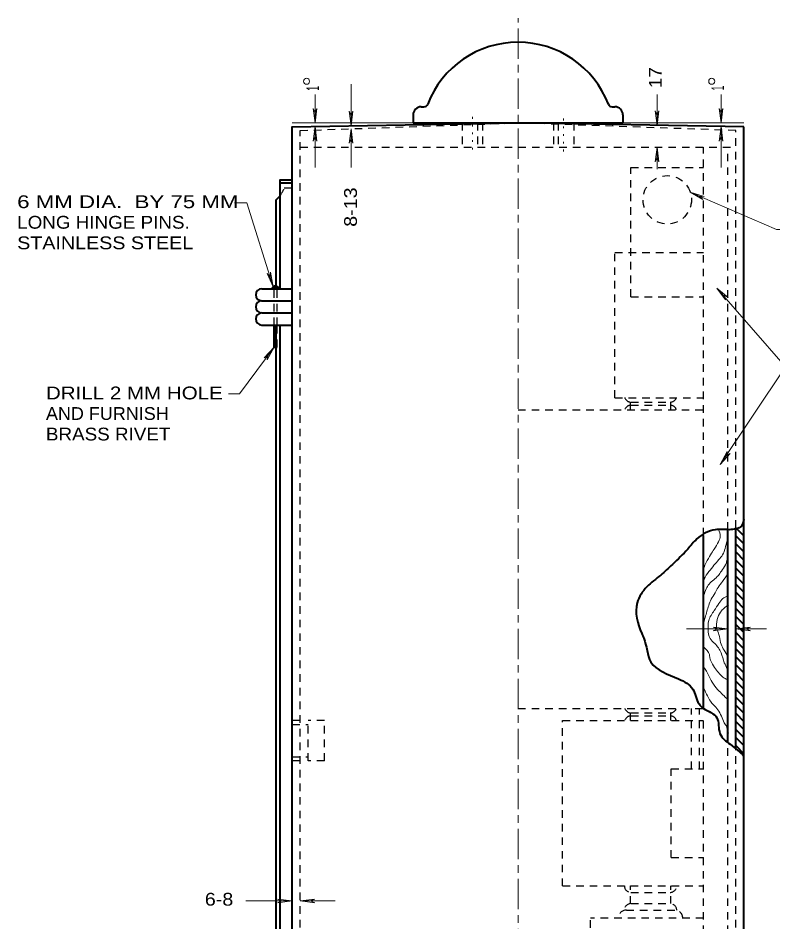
# Model space of a CAD drawing. Extents: x 312583 to 312853, y 144419 to 144586.
# Drawn here: x 312673.6 to 312718.5, y 144473.4 to 144527 of the extents above; entities that cross this region are included whole.
import ezdxf

# ---------------------------------------------------------------- set-up
doc = ezdxf.new("R2010")
doc.units = 0
doc.header["$LTSCALE"] = 0.3
for name, pattern in [('DOTTED', [1.5, 0.3, -1.2]), ('LONG_DASH_SHORT_DASH', [9.9, 6, -1.2, 1.5, -1.2]), ('SHORT_DASHED', [2.7, 1.5, -1.2])]:
    doc.linetypes.add(name, pattern=pattern)
doc.layers.add('1', color=7, linetype='Continuous', lineweight=13)

msp = doc.modelspace()

# ---------------------------------------------------------------- linework, layer by layer
at = {"layer": '1', "linetype": 'LONG_DASH_SHORT_DASH'}
msp.add_line((312703.3115, 144441.4612), (312703.3115, 144527.0365), dxfattribs=at)
at = {"layer": '1'}
for p, q in [((312693.3909, 144520.6349), (312693.3909, 144523.1046)), ((312691.2519, 144520.8112), (312691.2519, 144522.5055)), ((312711.5685, 144520.6655), (312711.5685, 144522.5055)), ((312715.3712, 144520.8112), (312715.3712, 144522.5055)), ((312691.1445, 144521.6775), (312691.2519, 144521.4015)), ((312691.2519, 144520.8112), (312691.1445, 144521.6775)), ((312691.3592, 144521.6775), (312691.2519, 144521.4015)), ((312691.2519, 144520.8112), (312691.3592, 144521.6775)), ((312693.2835, 144521.5012), (312693.3909, 144521.2252)), ((312693.3909, 144520.6349), (312693.2835, 144521.5012)), ((312693.4982, 144521.5012), (312693.3909, 144521.2252)), ((312693.3909, 144520.6349), (312693.4982, 144521.5012)), ((312711.4612, 144521.5319), (312711.5685, 144521.2559)), ((312711.5685, 144520.6655), (312711.4612, 144521.5319)), ((312711.6759, 144521.5319), (312711.5685, 144521.2559)), ((312711.5685, 144520.6655), (312711.6759, 144521.5319)), ((312715.2639, 144521.6775), (312715.3712, 144521.4015)), ((312715.3712, 144520.8112), (312715.2639, 144521.6775)), ((312715.4785, 144521.6775), (312715.3712, 144521.4015)), ((312715.3712, 144520.8112), (312715.4785, 144521.6775)), ((312703.3115, 144520.8112), (312689.8949, 144520.8112)), ((312703.3115, 144520.8112), (312716.7282, 144520.8112)), ((312691.2519, 144520.5965), (312691.1445, 144519.7302)), ((312691.2519, 144518.1585), (312691.2519, 144520.5965)), ((312691.2519, 144520.5965), (312691.3592, 144519.7302)), ((312693.3909, 144520.4662), (312693.2835, 144519.5999)), ((312693.3909, 144518.1585), (312693.3909, 144520.4662)), ((312693.3909, 144520.4662), (312693.4982, 144519.5999)), ((312715.3712, 144520.5965), (312715.2639, 144519.7302)), ((312715.3712, 144518.1585), (312715.3712, 144520.5965)), ((312715.3712, 144520.5965), (312715.4785, 144519.7302)), ((312691.1445, 144519.7302), (312691.2519, 144520.0062)), ((312691.3592, 144519.7302), (312691.2519, 144520.0062)), ((312693.2835, 144519.5999), (312693.3909, 144519.8759)), ((312693.4982, 144519.5999), (312693.3909, 144519.8759)), ((312715.2639, 144519.7302), (312715.3712, 144520.0062)), ((312715.4785, 144519.7302), (312715.3712, 144520.0062)), ((312711.5685, 144519.3699), (312711.4612, 144518.5035)), ((312711.5685, 144518.0742), (312711.5685, 144519.3699)), ((312711.5685, 144519.3699), (312711.6759, 144518.5035)), ((312711.4612, 144518.5035), (312711.5685, 144518.7795)), ((312711.6759, 144518.5035), (312711.5685, 144518.7795)), ((312713.5389, 144516.7095), (312714.2803, 144516.256)), ((312713.5389, 144516.7095), (312714.3663, 144516.4486)), ((312714.2803, 144516.256), (312714.0782, 144516.4665)), ((312714.3663, 144516.4486), (312714.0782, 144516.4665)), ((312686.4692, 144516.0732), (312687.2039, 144516.0732)), ((312688.7679, 144511.0822), (312687.2039, 144516.0732)), ((312688.4075, 144511.8795), (312688.5915, 144511.6419)), ((312688.7679, 144511.0822), (312688.4075, 144511.8795)), ((312688.6145, 144511.9409), (312688.5915, 144511.6419)), ((312688.7679, 144511.0822), (312688.6145, 144511.9409)), ((312715.1259, 144511.0055), (312715.6319, 144510.3002)), ((312715.1259, 144511.0055), (312715.7929, 144510.4459)), ((312715.6319, 144510.3002), (312715.5245, 144510.5762)), ((312715.7929, 144510.4459), (312715.5245, 144510.5762)), ((312688.8292, 144507.5019), (312686.7669, 144504.7265)), ((312688.8292, 144507.5019), (312688.2312, 144506.8655)), ((312688.8292, 144507.5019), (312688.3999, 144506.7429)), ((312688.2312, 144506.8655), (312688.4765, 144507.0265)), ((312688.3999, 144506.7429), (312688.4765, 144507.0265)), ((312686.1188, 144504.7265), (312686.7669, 144504.7265)), ((312715.3175, 144500.5329), (312715.7315, 144501.2995)), ((312715.3175, 144500.5329), (312715.9079, 144501.1769)), ((312715.7315, 144501.2995), (312715.6625, 144501.0159)), ((312715.9079, 144501.1769), (312715.6625, 144501.0159)), ((312713.3242, 144490.7655), (312715.7699, 144490.7655)), ((312714.9035, 144490.8729), (312715.1795, 144490.7655)), ((312715.7699, 144490.7655), (312714.9035, 144490.8729)), ((312714.9035, 144490.6582), (312715.1795, 144490.7655)), ((312715.7699, 144490.7655), (312714.9035, 144490.6582)), ((312716.2452, 144490.7655), (312717.1115, 144490.8729)), ((312716.2452, 144490.7655), (312718.0775, 144490.7655)), ((312716.2452, 144490.7655), (312717.1115, 144490.6582)), ((312717.1115, 144490.8729), (312716.8355, 144490.7655)), ((312717.1115, 144490.6582), (312716.8355, 144490.7655)), ((312687.1326, 144474.6195), (312689.8949, 144474.6195)), ((312689.0285, 144474.7269), (312689.3045, 144474.6195)), ((312689.8949, 144474.6195), (312689.0285, 144474.7269)), ((312689.0285, 144474.5122), (312689.3045, 144474.6195)), ((312689.8949, 144474.6195), (312689.0285, 144474.5122)), ((312690.3702, 144474.6195), (312691.2365, 144474.7269)), ((312690.3702, 144474.6195), (312692.4477, 144474.6195)), ((312690.3702, 144474.6195), (312691.2365, 144474.5122)), ((312691.2365, 144474.7269), (312690.9605, 144474.6195)), ((312691.2365, 144474.5122), (312690.9605, 144474.6195))]:
    msp.add_line(p, q, dxfattribs=at)
at = {"layer": '1', "lineweight": 40}
for p, q in [((312697.5615, 144521.7695), (312697.7225, 144521.7695)), ((312708.9005, 144521.7695), (312709.0615, 144521.7695)), ((312697.0785, 144521.2865), (312697.0785, 144520.8112)), ((312709.5369, 144521.2865), (312709.5369, 144520.8112)), ((312697.0785, 144520.8112), (312709.5369, 144520.8112)), ((312697.0785, 144520.8112), (312709.5369, 144520.8112)), ((312716.7282, 144520.5735), (312703.3115, 144520.8112)), ((312716.7282, 144443.8839), (312716.7282, 144520.5735)), ((312689.1742, 144517.2615), (312689.8949, 144517.2615)), ((312689.5192, 144517.4379), (312689.8949, 144517.4379)), ((312688.9365, 144510.9672), (312688.9365, 144516.2419)), ((312688.0932, 144510.9672), (312689.8949, 144510.9672)), ((312688.0932, 144510.2465), (312689.8949, 144510.2465)), ((312688.0932, 144509.5335), (312689.8949, 144509.5335)), ((312688.0932, 144508.8129), (312689.8949, 144508.8129)), ((312688.8292, 144507.5019), (312688.8292, 144508.8129)), ((312688.9365, 144462.3299), (312688.9365, 144508.8129)), ((312689.1742, 144462.3299), (312689.1742, 144508.8129)), ((312688.8292, 144507.5019), (312689.0132, 144507.5019)), ((312715.7699, 144484.0649), (312715.7699, 144496.6612)), ((312716.2452, 144483.6509), (312716.2452, 144496.7762)), ((312716.2452, 144496.7762), (312716.7282, 144496.3009)), ((312714.3285, 144486.0505), (312714.3285, 144496.3162)), ((312716.2452, 144496.3009), (312716.7282, 144495.8179)), ((312716.2452, 144495.8179), (312716.7282, 144495.3425)), ((312716.2452, 144495.3425), (312716.7282, 144494.8595)), ((312716.2452, 144494.8595), (312716.7282, 144494.3842)), ((312716.2452, 144494.3842), (312716.7282, 144493.9012)), ((312716.2452, 144493.9012), (312716.7282, 144493.4259)), ((312716.2452, 144493.4259), (312716.7282, 144492.9429)), ((312716.2452, 144492.9429), (312716.7282, 144492.4675)), ((312716.2452, 144492.4675), (312716.7282, 144491.9845)), ((312716.2452, 144491.9845), (312716.7282, 144491.5092)), ((312716.2452, 144491.5092), (312716.7282, 144491.0262)), ((312716.2452, 144491.0262), (312716.7282, 144490.5509)), ((312716.2452, 144490.5509), (312716.7282, 144490.0679)), ((312716.2452, 144490.0679), (312716.7282, 144489.5925)), ((312716.2452, 144489.5925), (312716.7282, 144489.1095)), ((312716.2452, 144489.1095), (312716.7282, 144488.6342)), ((312716.2452, 144488.6342), (312716.7282, 144488.1512)), ((312716.2452, 144488.1512), (312716.7282, 144487.6759)), ((312716.2452, 144487.6759), (312716.7282, 144487.1929)), ((312716.2452, 144487.1929), (312716.7282, 144486.7175)), ((312716.2452, 144486.7175), (312716.7282, 144486.2345)), ((312716.2452, 144486.2345), (312716.7282, 144485.7592)), ((312716.2452, 144485.7592), (312716.7282, 144485.2762)), ((312716.2452, 144485.2762), (312716.7282, 144484.8009)), ((312716.2452, 144484.8009), (312716.7282, 144484.3179)), ((312716.2452, 144484.3179), (312716.7282, 144483.8425)), ((312716.2452, 144483.8425), (312716.7282, 144483.3595))]:
    msp.add_line(p, q, dxfattribs=at)
at = {"layer": '1', "linetype": 'SHORT_DASHED', "lineweight": 25}
for p, q in [((312690.3702, 144520.3589), (312703.3115, 144520.8112)), ((312699.9995, 144520.8112), (312699.9995, 144519.3699)), ((312700.9119, 144520.8112), (312700.9119, 144519.3699)), ((312701.2032, 144520.8112), (312701.2032, 144519.3699)), ((312716.2452, 144520.3589), (312703.3115, 144520.8112)), ((312705.4199, 144520.8112), (312705.4199, 144519.3699)), ((312705.7035, 144520.8112), (312705.7035, 144519.3699)), ((312706.6235, 144520.8112), (312706.6235, 144519.3699)), ((312690.3702, 144443.8839), (312690.3702, 144520.3589)), ((312716.2452, 144496.7762), (312716.2452, 144520.3589)), ((312690.3702, 144519.3699), (312716.2452, 144519.3699)), ((312714.3285, 144496.3162), (312714.3285, 144519.3699)), ((312715.7699, 144496.6612), (312715.7699, 144519.3699)), ((312689.4272, 144516.9549), (312689.8949, 144516.9549)), ((312709.0615, 144513.1215), (312714.3285, 144513.1215)), ((312709.0615, 144504.4965), (312709.0615, 144513.1215)), ((312688.8292, 144508.8129), (312688.8292, 144510.9672)), ((312689.0132, 144508.8129), (312689.0132, 144510.9672)), ((312710.0199, 144510.4919), (312714.3285, 144510.4919)), ((312689.0132, 144507.5019), (312689.0132, 144508.8129)), ((312709.0615, 144504.4965), (312714.3285, 144504.4965)), ((312709.9815, 144503.7835), (312709.9815, 144504.4965)), ((312710.0199, 144504.2282), (312712.3505, 144504.2282)), ((312712.3812, 144503.7835), (312712.3812, 144504.4965)), ((312703.3115, 144503.7835), (312714.3285, 144503.7835)), ((312710.0199, 144504.0519), (312712.3505, 144504.0519)), ((312703.3115, 144486.0505), (312714.3285, 144486.0505)), ((312709.9815, 144485.3299), (312709.9815, 144486.0505)), ((312712.3812, 144485.3299), (312712.3812, 144486.0505)), ((312713.6155, 144482.4549), (312713.6155, 144486.0505)), ((312714.0909, 144482.4549), (312714.0909, 144486.0505)), ((312690.3702, 144485.3299), (312689.8949, 144485.3299)), ((312690.8532, 144482.9379), (312690.8532, 144485.3299)), ((312691.8115, 144485.3299), (312690.8532, 144485.3299)), ((312691.8115, 144482.9379), (312691.8115, 144485.3299)), ((312705.9489, 144485.3299), (312714.3285, 144485.3299)), ((312705.9489, 144475.5089), (312705.9489, 144485.3299)), ((312710.0199, 144485.7822), (312712.3505, 144485.7822)), ((312710.0199, 144485.6059), (312712.3505, 144485.6059)), ((312714.3285, 144450.8299), (312714.3285, 144485.2992)), ((312689.8949, 144485.0922), (312690.8532, 144485.0922)), ((312715.7699, 144450.8299), (312715.7699, 144484.0649)), ((312689.8949, 144483.1755), (312690.8532, 144483.1755)), ((312716.2452, 144443.8839), (312716.2452, 144483.6509)), ((312690.3702, 144482.9379), (312689.8949, 144482.9379)), ((312691.8115, 144482.9379), (312690.8532, 144482.9379)), ((312712.4119, 144477.1879), (312712.4119, 144482.4549)), ((312712.4119, 144482.4549), (312714.3285, 144482.4549)), ((312712.4119, 144477.1879), (312714.3285, 144477.1879)), ((312705.9489, 144475.5089), (312714.3285, 144475.5089)), ((312709.9815, 144474.4585), (312709.9815, 144475.5089)), ((312710.0199, 144475.1179), (312712.3505, 144475.1179)), ((312712.3812, 144474.4585), (312712.3812, 144475.5089)), ((312709.7439, 144474.0752), (312712.6189, 144474.0752)), ((312710.0199, 144474.4585), (312712.3505, 144474.4585)), ((312714.3285, 144473.5922), (312707.6202, 144473.5922)), ((312707.6202, 144456.8252), (312707.6202, 144473.5922))]:
    msp.add_line(p, q, dxfattribs=at)
at = {"layer": '1', "linetype": 'DOTTED'}
for p, q in [((312700.5975, 144521.1639), (312700.5975, 144518.9865)), ((312706.0179, 144521.0642), (312706.0179, 144518.9865))]:
    msp.add_line(p, q, dxfattribs=at)
at = {"layer": '1', "lineweight": 40}
for points in [[(312689.8949, 144445.5629), (312689.8949, 144520.5735), (312703.3115, 144520.8112)], [(312689.1742, 144510.9672), (312689.1742, 144517.4379), (312689.8949, 144517.4379)]]:
    msp.add_lwpolyline(points, dxfattribs=at)
at = {"layer": '1', "linetype": 'SHORT_DASHED', "lineweight": 25}
msp.add_lwpolyline([(312710.0199, 144510.4919), (312710.0199, 144518.1585), (312714.3285, 144518.1585)], dxfattribs=at)
at = {"layer": '1'}
for points in [[(312713.5389, 144516.7095), (312718.6645, 144514.4903), (312719.5229, 144514.4903)], [(312715.3175, 144500.5329), (312719.1969, 144506.3289), (312715.1259, 144511.0055)]]:
    msp.add_lwpolyline(points, dxfattribs=at)
for centre in [(312690.7479, 144523.2873), (312714.8174, 144523.2873)]:
    msp.add_circle(centre, 0.1797, dxfattribs=at)
at = {"layer": '1', "linetype": 'SHORT_DASHED', "lineweight": 25}
msp.add_circle((312712.1742, 144516.2495), 1.4375, dxfattribs=at)
at = {"layer": '1', "lineweight": 40}
for centre, radius, start, end in [((312703.3096, 144519.8529), 5.75, 21.1002, 158.90079), ((312697.5596, 144521.2904), 0.4792, 90, 180), ((312697.7216, 144522.0091), 0.2396, 270, 338.8998), ((312708.8976, 144522.0091), 0.2396, 201.1002, 270), ((312709.0596, 144521.2904), 0.4792, 0, 90), ((312687.8295, 144517.5217), 1.6924, 310.76787, 322.61369), ((312688.9135, 144510.8849), 0.2436, 20.21131, 159.74458), ((312688.9188, 144510.906), 0.1827, 20.21131, 159.74458), ((312688.9228, 144510.9218), 0.137, 20.21131, 159.74458), ((312688.9257, 144510.9336), 0.1028, 20.21131, 159.74458), ((312688.0961, 144510.6097), 0.3594, 90.15279, 269.84721), ((312688.0961, 144509.891), 0.3594, 90.15279, 269.84721), ((312688.0961, 144509.1722), 0.3594, 90.15279, 269.84721)]:
    msp.add_arc(centre, radius, start, end, dxfattribs=at)
at = {"layer": '1', "linetype": 'SHORT_DASHED', "lineweight": 25}
for centre, radius, start, end in [((312687.8295, 144517.5217), 1.6924, 322.63412, 340.56673), ((312710.0181, 144504.6204), 0.3881, 198.00716, 269.9802), ((312712.3468, 144504.6204), 0.3881, 269.9802, 341.99284), ((312710.0181, 144503.6635), 0.3881, 90.0198, 161.99284), ((312712.3468, 144503.6635), 0.3881, 18.00716, 90.0198), ((312710.0181, 144486.1724), 0.3881, 198.00716, 269.9802), ((312712.3468, 144486.1724), 0.3881, 269.9802, 341.99284), ((312710.0181, 144485.2156), 0.3881, 90.0198, 161.99284), ((312712.3468, 144485.2156), 0.3881, 18.00716, 90.0198), ((312710.0181, 144475.51), 0.3881, 180, 270), ((312712.3468, 144475.51), 0.3881, 270, 0), ((312709.7439, 144473.5941), 0.4792, 90, 180), ((312710.0181, 144474.074), 0.3881, 90, 180), ((312712.3468, 144474.074), 0.3881, 0, 90), ((312712.6189, 144473.5941), 0.4792, 0, 90)]:
    msp.add_arc(centre, radius, start, end, dxfattribs=at)
at = {"layer": '1', "lineweight": 40}
msp.add_spline([(312716.7282, 144497.2669), (312716.5749, 144496.8759), (312715.8465, 144496.6612), (312715.0262, 144496.6612), (312713.9375, 144496.1169), (312713.3932, 144495.5112), (312712.4809, 144494.5989), (312711.7832, 144493.9625), (312710.9629, 144493.2649), (312710.3879, 144492.3219), (312710.6562, 144490.5049), (312710.7789, 144490.2289), (312711.2082, 144488.8029), (312712.8412, 144487.7985), (312713.6922, 144487.1929), (312714.0602, 144486.3112), (312714.3285, 144486.0505), (312715.1182, 144485.4985), (312715.3022, 144484.5555), (312715.9079, 144483.9192), (312716.3679, 144483.5512), (312716.7282, 144483.2215)], degree=3, dxfattribs=at)
at = {"layer": '1'}
for points in [[(312715.2255, 144496.6612), (312715.3175, 144496.2779), (312715.2255, 144495.9482), (312714.9649, 144495.5112), (312714.7502, 144495.1739), (312714.4895, 144494.7062), (312714.3439, 144494.4072)], [(312715.7239, 144496.0019), (312715.6089, 144495.5419), (312715.4632, 144495.1739), (312715.2409, 144494.8825), (312714.9495, 144494.5529), (312714.6429, 144494.1695), (312714.3669, 144493.7325), (312714.3515, 144493.6789)], [(312715.7392, 144494.9132), (312715.6319, 144494.5759), (312715.3865, 144494.2002), (312715.2102, 144493.9395), (312714.6582, 144493.4335), (312714.4895, 144493.1422), (312714.3439, 144492.7742)], [(312715.7545, 144494.0239), (312715.4632, 144493.5869), (312715.1949, 144493.2265), (312715.0109, 144492.9045), (312714.7885, 144492.5289), (312714.6352, 144492.1685), (312714.5279, 144491.8005), (312714.4282, 144491.4555), (312714.3439, 144491.1489)], [(312715.7622, 144492.7282), (312715.4785, 144492.5749), (312715.2409, 144492.2835), (312714.9649, 144491.8619), (312714.6352, 144491.2639), (312714.6045, 144490.7425), (312714.7195, 144490.1982), (312714.9955, 144489.8992), (312715.3712, 144489.3472), (312715.5629, 144488.7645), (312715.7545, 144488.3812)], [(312715.8082, 144492.2069), (312715.3405, 144491.7699), (312715.1412, 144491.3329), (312715.1259, 144490.7809), (312715.2409, 144490.4359), (312715.3405, 144489.9529), (312715.5015, 144489.5925), (312715.7239, 144489.2169), (312715.7545, 144489.1555)], [(312714.3515, 144489.6769), (312714.6735, 144489.2552), (312714.7042, 144489.0559), (312714.8192, 144488.7645), (312715.0415, 144488.3965), (312715.2869, 144488.1052), (312715.4785, 144487.9059), (312715.7545, 144487.7602)], [(312714.3515, 144488.5115), (312714.4972, 144488.2509), (312714.6582, 144487.9519), (312714.9189, 144487.4842), (312715.2562, 144487.0779), (312715.5475, 144486.7865), (312715.7545, 144486.5795)], [(312714.3515, 144487.2465), (312714.5585, 144486.7865), (312714.7349, 144486.4799), (312714.9342, 144486.2499), (312715.1719, 144485.9739), (312715.3865, 144485.5905), (312715.5629, 144485.1842), (312715.6932, 144484.9695), (312715.7392, 144484.7932), (312715.8082, 144484.5862)]]:
    msp.add_spline(points, degree=3, dxfattribs=at)

# ---------------------------------------------------------------- texts
for s, width, p in [('17 ', 1.1, (312711.8457, 144522.8812)), ('1', 0.5, (312691.4918, 144522.7267)), ('1', 0.5, (312715.551, 144522.7409)), (' 8-13', 1.15, (312693.7403, 144514.3182))]:
    msp.add_text(s, height=0.76, rotation=90, dxfattribs=dict(at, width=width)).set_placement(p)
for s, width, p in [('6 MM DIA.  BY 75 MM', 1.3, (312673.5606, 144515.7514)), ('LONG HINGE PINS.', 1.1, (312673.5606, 144514.5314)), ('STAINLESS STEEL', 1.15, (312673.5606, 144513.3114)), ('DRILL 2 MM HOLE', 1.2, (312675.2693, 144504.3971)), ('AND FURNISH', 1.05, (312675.2693, 144503.1771)), ('BRASS RIVET', 1.1, (312675.2693, 144501.9571)), ('6-8', 1.15, (312684.7071, 144474.3378))]:
    msp.add_text(s, height=0.76, dxfattribs=dict(at, width=width)).set_placement(p)

doc.saveas('drawing.dxf')
